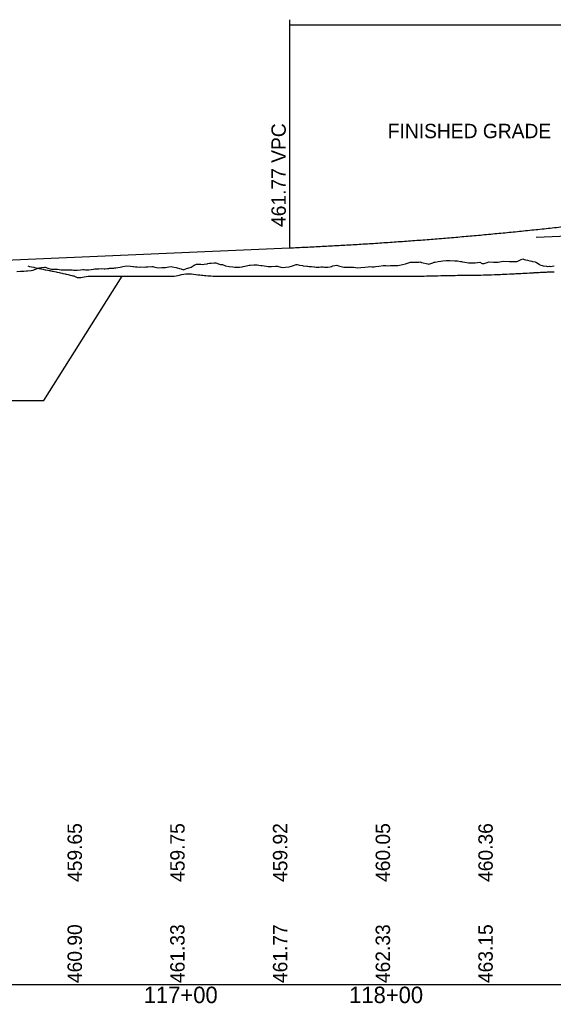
# Model space of a CAD drawing. Extents: x 2017200 to 2047700, y 854850 to 893350.
# Drawn here: x 2023118.7 to 2023378.5, y 862090.9 to 862570 of the extents above; entities that cross this region are included whole.
import ezdxf

# ---------------------------------------------------------------- set-up
doc = ezdxf.new("R2010")
doc.units = 0
for name, color, linetype in [('RD_DDB_GradeTX', 7, 'Continuous'), ('RD_DDB_Profile_Elev', 7, 'Continuous'), ('RD_DDB_Profile_EX', 7, 'Continuous'), ('RD_DDB_Profile_Lbl', 7, 'Continuous'), ('RD_DDB_Profile_PR', 7, 'Continuous'), ('RD_DDB_StaTX', 7, 'Continuous'), ('RD_DDB_StripGrade', 7, 'Continuous'), ('RD_DDB_VCLbl', 7, 'Continuous'), ('RD_GPK_Profile_Cell', 7, 'Continuous')]:
    doc.layers.add(name, color=color, linetype=linetype)

msp = doc.modelspace()

# ---------------------------------------------------------------- linework, layer by layer
at = {"layer": 'RD_DDB_GradeTX'}
msp.add_line((2023370.08, 862464.03), (2023450, 862467.5), dxfattribs=at)
at = {"layer": 'RD_DDB_Profile_Elev'}
for points in [[(2023122.72, 862450), (2023123.47, 862449.83), (2023124.4, 862449.61), (2023125.52, 862449.36), (2023125.96, 862449.25), (2023126.74, 862449.1), (2023128.02, 862448.84), (2023128.94, 862448.61), (2023129.4, 862448.56), (2023130.11, 862448.39), (2023130.47, 862448.36), (2023131.17, 862448.19), (2023131.51, 862448.16), (2023132.36, 862447.99), (2023133.09, 862447.85), (2023133.48, 862447.76), (2023133.94, 862447.67), (2023134.56, 862447.54), (2023135.07, 862447.44), (2023135.65, 862447.3), (2023136.4, 862447.15), (2023136.98, 862447.01), (2023138, 862446.79), (2023138.37, 862446.71), (2023139.33, 862446.5), (2023139.76, 862446.39), (2023140.77, 862446.17), (2023141.09, 862446.09), (2023141.45, 862446.01), (2023142.29, 862445.81), (2023143.31, 862445.57), (2023144.01, 862445.4), (2023144.5, 862445.28), (2023145.1, 862445.14), (2023146.61, 862444.37), (2023147.47, 862444.4), (2023148.53, 862444.43), (2023150.05, 862444.69), (2023151.99, 862445), (2023153.17, 862445), (2023153.49, 862445), (2023154.5, 862445), (2023155.21, 862445), (2023155.9, 862445), (2023157.28, 862445), (2023158.65, 862445), (2023159.48, 862445), (2023160.37, 862445), (2023161.08, 862445), (2023162.09, 862445), (2023163.13, 862445), (2023163.81, 862445), (2023164.45, 862445), (2023165.79, 862445), (2023167.25, 862445), (2023168.55, 862445), (2023168.97, 862445), (2023169.86, 862445), (2023171.04, 862445), (2023172.06, 862445), (2023172.69, 862445), (2023173.47, 862445), (2023174.45, 862445), (2023175.85, 862445), (2023176.94, 862445), (2023177.57, 862445), (2023178.57, 862445), (2023179.29, 862445), (2023179.71, 862445), (2023180.02, 862445), (2023181.11, 862445), (2023181.47, 862445), (2023182.73, 862445), (2023183.29, 862445), (2023183.7, 862445), (2023184.45, 862445), (2023184.8, 862445), (2023185.28, 862445), (2023185.73, 862445), (2023186.19, 862445), (2023186.82, 862445), (2023187.23, 862445), (2023187.57, 862445), (2023187.89, 862445), (2023188.25, 862445), (2023188.61, 862445), (2023189.17, 862445), (2023189.79, 862445), (2023190.54, 862445), (2023191.33, 862445), (2023191.99, 862445), (2023192.31, 862445), (2023193.05, 862445), (2023193.56, 862445), (2023193.97, 862445), (2023194.91, 862445.21), (2023196.49, 862445.57), (2023197.55, 862445.8), (2023198.63, 862446.02), (2023199.53, 862446.2), (2023200.06, 862446.26), (2023200.74, 862446.25), (2023201.65, 862446.18), (2023202.41, 862446.11), (2023203.4, 862445.99), (2023204.42, 862445.87), (2023205.42, 862445.75), (2023206.34, 862445.63), (2023207.15, 862445.53), (2023207.8, 862445.47), (2023208.53, 862445.4), (2023209.31, 862445.34), (2023210.37, 862445.25), (2023211.57, 862445.16), (2023211.97, 862445.13), (2023212.84, 862445.07), (2023214.15, 862445), (2023215.45, 862445), (2023216.68, 862445), (2023217.14, 862445), (2023217.78, 862445), (2023218.86, 862445), (2023219.3, 862445), (2023220.05, 862445), (2023220.95, 862445), (2023222.3, 862445), (2023223.17, 862445), (2023224.36, 862445), (2023225.74, 862445), (2023226.77, 862445), (2023227.9, 862445), (2023228.61, 862445), (2023229.45, 862445), (2023229.98, 862445), (2023230.99, 862445), (2023232.13, 862445), (2023232.62, 862445), (2023233.34, 862445), (2023234.72, 862445), (2023236.06, 862445), (2023237.78, 862445), (2023238.66, 862445), (2023239.83, 862445), (2023240.82, 862445), (2023241.45, 862445), (2023242.16, 862445), (2023243.04, 862445), (2023243.96, 862445), (2023244.66, 862445), (2023245.07, 862445), (2023246.38, 862445), (2023247.42, 862445), (2023248.1, 862445), (2023248.6, 862445), (2023249.82, 862445), (2023250.68, 862445), (2023251.54, 862445.02), (2023252.19, 862445.03), (2023252.86, 862445.01), (2023253.26, 862445), (2023253.76, 862445), (2023254.98, 862445), (2023256.03, 862445), (2023256.7, 862445), (2023257.32, 862445), (2023258.59, 862445), (2023260.14, 862445), (2023261.04, 862445), (2023262.14, 862445), (2023263.09, 862445), (2023263.72, 862445), (2023264.49, 862445), (2023265.46, 862445), (2023266.46, 862445), (2023267.02, 862445), (2023267.8, 862445), (2023269.07, 862445), (2023270.46, 862445), (2023271.67, 862445), (2023272.18, 862445), (2023272.88, 862445), (2023274, 862445), (2023274.97, 862445), (2023275.71, 862445), (2023276.35, 862445), (2023276.92, 862445), (2023277.84, 862445), (2023279.16, 862445), (2023280.59, 862445), (2023281.14, 862445), (2023282.07, 862445), (2023283.53, 862445), (2023284.97, 862445), (2023286.26, 862445), (2023287.3, 862445), (2023288.38, 862445), (2023289.06, 862445), (2023290.08, 862445), (2023291.41, 862445), (2023292, 862445), (2023292.89, 862445), (2023294.46, 862445), (2023295.62, 862445), (2023296.06, 862445), (2023297.62, 862445), (2023299.24, 862445), (2023300.45, 862445), (2023301.58, 862445), (2023302.39, 862445), (2023302.85, 862445), (2023303.29, 862445), (2023304.48, 862445), (2023305.9, 862445), (2023306.47, 862445), (2023307.48, 862445), (2023309.15, 862445), (2023310.09, 862445), (2023310.86, 862445), (2023312.53, 862445), (2023313.71, 862445.04), (2023314.12, 862445.05), (2023315.55, 862445.1), (2023316.7, 862445.14), (2023317.6, 862445.16), (2023318.41, 862445.18), (2023319.54, 862445.21), (2023320.95, 862445.25), (2023322.3, 862445.28), (2023323.81, 862445.32), (2023324.57, 862445.33), (2023325.38, 862445.35), (2023326.88, 862445.38), (2023328.31, 862445.41), (2023329.62, 862445.43), (2023330.76, 862445.45), (2023331.8, 862445.47), (2023332.46, 862445.48), (2023333.65, 862445.5), (2023335.05, 862445.51), (2023335.42, 862445.52), (2023336.58, 862445.53), (2023338.26, 862445.55), (2023339.04, 862445.56), (2023339.98, 862445.57), (2023341.6, 862445.58), (2023342.66, 862445.59), (2023343.15, 862445.6), (2023344.56, 862445.62), (2023345.57, 862445.63), (2023346.53, 862445.65), (2023347.47, 862445.68), (2023348.41, 862445.72), (2023349.9, 862445.79), (2023351.13, 862445.84), (2023352.72, 862445.91), (2023353.52, 862445.95), (2023354.37, 862445.99), (2023355.57, 862446.04), (2023355.87, 862446.06), (2023357.34, 862446.14), (2023358.33, 862446.18), (2023359.15, 862446.22), (2023359.57, 862446.25), (2023360.19, 862446.28), (2023360.84, 862446.31), (2023361.3, 862446.34), (2023362.17, 862446.38), (2023362.65, 862446.41), (2023363.7, 862446.47), (2023364.37, 862446.51), (2023365.32, 862446.56), (2023365.77, 862446.58), (2023366.96, 862446.65), (2023367.36, 862446.67), (2023367.99, 862446.7), (2023368.53, 862446.73), (2023368.84, 862446.75), (2023369.16, 862446.76), (2023370.28, 862446.82), (2023370.72, 862446.84), (2023371.25, 862446.87), (2023371.61, 862446.88), (2023372.28, 862446.92), (2023372.9, 862446.95), (2023373.79, 862446.99), (2023374.51, 862447.02), (2023375.23, 862447.06), (2023375.71, 862447.08), (2023376.19, 862447.1), (2023376.92, 862447.13), (2023377.53, 862447.16), (2023378.28, 862447.19), (2023378.98, 862447.22)], [(2023104.8, 862384.41), (2023130.4, 862384.41), (2023168.55, 862445)]]:
    msp.add_lwpolyline(points, dxfattribs=at)
at = {"layer": 'RD_DDB_Profile_EX'}
msp.add_lwpolyline([(2023117.36, 862447.29), (2023119.08, 862447.47), (2023119.67, 862447.43), (2023120.8, 862447.51), (2023122.08, 862447.59), (2023122.52, 862447.7), (2023124.24, 862447.88), (2023125.24, 862448), (2023125.96, 862448.29), (2023126.82, 862448.64), (2023127.68, 862448.96), (2023128.11, 862449.09), (2023129.4, 862449.27), (2023130.73, 862449.45), (2023131.12, 862449.45), (2023132.84, 862448.8), (2023133.46, 862448.57), (2023134.14, 862448.46), (2023134.56, 862448.44), (2023136.28, 862448.38), (2023137.16, 862448.42), (2023138, 862448.26), (2023138.86, 862448.1), (2023139.72, 862448.13), (2023140.19, 862448.15), (2023141.54, 862448.2), (2023143.21, 862448.17), (2023144.2, 862448.07), (2023144.89, 862448.01), (2023146.24, 862447.89), (2023146.61, 862447.94), (2023148.33, 862448.19), (2023149.48, 862448.32), (2023150.05, 862448.27), (2023150.77, 862448.2), (2023151.77, 862448.14), (2023152.32, 862448.05), (2023153.49, 862448.27), (2023154.71, 862448.51), (2023155.36, 862448.69), (2023156.93, 862448.62), (2023157.31, 862448.61), (2023158.65, 862448.7), (2023159.89, 862448.55), (2023160.37, 862448.61), (2023161.46, 862448.74), (2023162.09, 862448.82), (2023162.46, 862448.87), (2023163.81, 862448.92), (2023164.51, 862448.94), (2023165.01, 862449.07), (2023165.53, 862449.14), (2023167.6, 862449.45), (2023168.97, 862449.74), (2023170.69, 862450.08), (2023172.62, 862449.85), (2023173.71, 862449.81), (2023174.13, 862449.74), (2023175.13, 862449.59), (2023175.85, 862449.54), (2023176.79, 862449.47), (2023177.63, 862449.53), (2023179.29, 862449.51), (2023180.12, 862449.55), (2023181.15, 862449.67), (2023182.96, 862449.74), (2023183.56, 862449.72), (2023184.45, 862449.5), (2023186.17, 862449.11), (2023187.89, 862449.2), (2023189.16, 862449.23), (2023189.61, 862449.32), (2023191.33, 862449.67), (2023192.43, 862449.82), (2023193.05, 862449.64), (2023194.87, 862449.2), (2023195.39, 862449.12), (2023196.49, 862448.78), (2023197.29, 862448.54), (2023198.51, 862448.2), (2023199.93, 862448.74), (2023201.65, 862449.28), (2023202.11, 862449.46), (2023203.64, 862450.4), (2023204.78, 862450.89), (2023205.3, 862450.95), (2023206.81, 862450.86), (2023207.93, 862450.79), (2023208.53, 862450.88), (2023209.95, 862451.11), (2023210.25, 862451.19), (2023211.09, 862451.42), (2023211.97, 862451.45), (2023213.37, 862451.5), (2023213.7, 862451.51), (2023214.26, 862451.51), (2023215.42, 862451.11), (2023216.39, 862450.77), (2023217.43, 862450.69), (2023218.86, 862450.12), (2023220.62, 862449.79), (2023222.4, 862449.54), (2023223.43, 862449.41), (2023224.02, 862449.39), (2023225.76, 862449.51), (2023227.02, 862449.65), (2023227.46, 862449.74), (2023229.18, 862450.12), (2023229.83, 862450.27), (2023230.41, 862450.4), (2023230.9, 862450.43), (2023232.62, 862450.53), (2023233.46, 862450.58), (2023234.34, 862450.5), (2023235.19, 862450.42), (2023236.06, 862450.29), (2023236.7, 862450.2), (2023237.78, 862450.07), (2023238.86, 862449.93), (2023239.63, 862449.78), (2023239.95, 862449.79), (2023240.73, 862449.8), (2023241.22, 862449.82), (2023243.21, 862449.88), (2023244.2, 862449.86), (2023244.66, 862449.74), (2023246.49, 862449.25), (2023248.1, 862449.41), (2023249.82, 862449.58), (2023251.02, 862449.84), (2023251.54, 862450.06), (2023253.28, 862450.76), (2023253.73, 862450.65), (2023254.98, 862450.43), (2023256.38, 862450.17), (2023256.7, 862450.13), (2023258.42, 862449.9), (2023258.77, 862449.85), (2023259.71, 862449.74), (2023260.14, 862449.72), (2023260.7, 862449.69), (2023261.86, 862449.66), (2023262.28, 862449.65), (2023263.05, 862449.51), (2023263.58, 862449.51), (2023264.52, 862449.51), (2023265.3, 862449.53), (2023266.41, 862449.55), (2023267.02, 862449.49), (2023267.42, 862449.41), (2023268.74, 862449.47), (2023269.78, 862449.52), (2023270.46, 862449.76), (2023271.2, 862450.02), (2023272.18, 862450.18), (2023273.17, 862450.34), (2023273.9, 862450.13), (2023276.57, 862449.46), (2023277.52, 862449.46), (2023279.58, 862449.46), (2023280.31, 862449.45), (2023281.14, 862449.4), (2023282.3, 862449.31), (2023283.36, 862449.14), (2023284.76, 862449.23), (2023286.76, 862449.35), (2023288.38, 862449.6), (2023288.97, 862449.69), (2023290.13, 862449.64), (2023291.2, 862449.59), (2023292, 862449.69), (2023293.51, 862449.91), (2023295.65, 862450.18), (2023296.89, 862450.22), (2023297.88, 862450.16), (2023299.24, 862450.22), (2023299.8, 862450.24), (2023300.26, 862450.24), (2023300.74, 862450.26), (2023302.85, 862450.31), (2023303.63, 862450.33), (2023306.47, 862451.11), (2023307, 862451.2), (2023309.03, 862451.88), (2023310.36, 862451.93), (2023311.26, 862451.92), (2023313.05, 862451.93), (2023313.72, 862451.96), (2023314.39, 862451.76), (2023317.33, 862451.05), (2023317.97, 862450.97), (2023319.76, 862451.56), (2023320.43, 862451.82), (2023320.95, 862451.9), (2023322.44, 862452.12), (2023323.78, 862452.38), (2023324.68, 862452.49), (2023326.52, 862452.66), (2023327.12, 862452.69), (2023327.71, 862452.67), (2023328.19, 862452.63), (2023330.47, 862452.48), (2023331.41, 862452.49), (2023331.8, 862452.44), (2023333.34, 862452.24), (2023333.8, 862452.18), (2023334.24, 862452.08), (2023335.42, 862451.85), (2023337.14, 862451.5), (2023339.04, 862451.49), (2023340.47, 862451.51), (2023342.66, 862451.9), (2023343.8, 862451.25), (2023344.89, 862451.2), (2023346.28, 862451.7), (2023347.16, 862452), (2023349.39, 862451.83), (2023349.9, 862451.82), (2023350.45, 862451.81), (2023351.64, 862451.84), (2023354.16, 862452.3), (2023357.14, 862452.21), (2023358.41, 862452.12), (2023360.76, 862452.21), (2023361.22, 862452.4), (2023362.92, 862453.2), (2023363.71, 862453.43), (2023364.37, 862453.24), (2023365.87, 862452.8), (2023367.02, 862452.49), (2023367.99, 862452.33), (2023368.36, 862452.27), (2023369.7, 862452.01), (2023370.32, 862451.68), (2023371.61, 862450.83), (2023371.96, 862450.6), (2023373.62, 862450.02), (2023375.23, 862449.85), (2023375.55, 862449.81), (2023376.49, 862449.86), (2023376.92, 862449.71), (2023378.85, 862450.02)], dxfattribs=at)
at = {"layer": 'RD_DDB_Profile_PR'}
msp.add_line((2022997.5, 862447.88), (2023250, 862458.83), dxfattribs=at)
msp.add_spline([(2023250, 862458.83), (2023258, 862459.19), (2023266, 862459.59), (2023274, 862460.02), (2023282, 862460.48), (2023290, 862460.97), (2023298, 862461.5), (2023306, 862462.07), (2023314, 862462.66), (2023322, 862463.29), (2023330, 862463.95), (2023338, 862464.64), (2023346, 862465.37), (2023354, 862466.13), (2023362, 862466.92), (2023370, 862467.75), (2023378, 862468.61), (2023386, 862469.5), (2023394, 862470.42), (2023402, 862471.38), (2023410, 862472.37), (2023418, 862473.4), (2023426, 862474.45), (2023434, 862475.54), (2023442, 862476.67), (2023450, 862477.82), (2023458, 862479.01), (2023466, 862480.24), (2023474, 862481.49), (2023482, 862482.78), (2023490, 862484.1), (2023498, 862485.46), (2023506, 862486.84), (2023514, 862488.26), (2023522, 862489.72), (2023530, 862491.2), (2023538, 862492.72), (2023546, 862494.28), (2023554, 862495.86), (2023562, 862497.48), (2023570, 862499.13), (2023578, 862500.82), (2023586, 862502.54), (2023594, 862504.29), (2023602, 862506.07), (2023610, 862507.89), (2023618, 862509.74), (2023626, 862511.62), (2023634, 862513.54), (2023642, 862515.49), (2023650, 862517.47)], degree=3, dxfattribs=at)
at = {"layer": 'RD_DDB_VCLbl'}
for p, q in [((2023250, 862569.97), (2023250, 862458.83)), ((2023250, 862567.47), (2023650, 862567.47))]:
    msp.add_line(p, q, dxfattribs=at)
at = {"layer": 'RD_GPK_Profile_Cell'}
msp.add_line((2020500, 862100), (2024800, 862100), dxfattribs=at)

# ---------------------------------------------------------------- texts
at = {"layer": 'RD_DDB_Profile_Lbl'}
msp.add_text('FINISHED GRADE', height=7, dxfattribs=at).set_placement((2023297.9, 862512.25))
at = {"layer": 'RD_DDB_StaTX'}
for s, p in [('117+00', (2023179.1, 862091)), ('118+00', (2023279.1, 862091))]:
    msp.add_text(s, height=8, dxfattribs=at).set_placement(p)
at = {"layer": 'RD_DDB_StripGrade'}
for s, p in [('461.77 VPC', (2023248.26, 862469.01)), ('459.65', (2023149, 862150)), ('459.75', (2023199, 862150)), ('459.92', (2023249, 862150)), ('460.05', (2023299, 862150)), ('460.36', (2023349, 862150)), ('460.90', (2023149, 862100.75)), ('461.33', (2023199, 862100.75)), ('461.77', (2023249, 862100.75)), ('462.33', (2023299, 862100.75)), ('463.15', (2023349, 862100.75))]:
    msp.add_text(s, height=7, rotation=90, dxfattribs=at).set_placement(p)

doc.saveas('drawing.dxf')
